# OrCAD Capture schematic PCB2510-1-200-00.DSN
size Custom; title: .; rev: 00; note: NFC EXPANSION BOARD OM5578/PN7150S
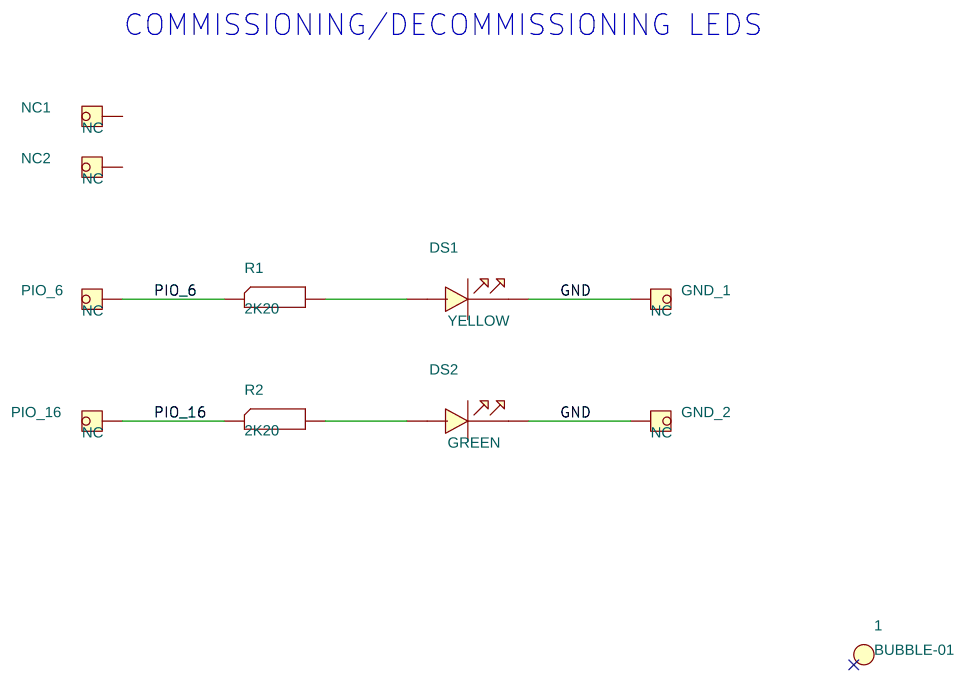
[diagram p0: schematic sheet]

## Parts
1  BUBBLE-01  [BUBBLE_DIAM8]
DS1  YELLOW  [LED_0603_A_K]
DS2  GREEN  [LED_0603_A_K]
GND_1  NC  [TROU1MM1_PAST1MM6]
GND_2  NC  [TROU1MM1_PAST1MM6]
NC1  NC  [TROU1MM1_PAST1MM6]
NC2  NC  [TROU1MM1_PAST1MM6]
PIO_6  NC  [TROU1MM1_PAST1MM6]
PIO_16  NC  [TROU1MM1_PAST1MM6]
R1  2K20  [R0603]
R2  2K20  [R0603]

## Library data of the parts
1 = BUBBLE: Designation: Printed_Circuit_Board:PCB2510-1; Manufacturer_reference: PCB2510-1; Part Number: CI-PCB2510-1; Part Type: BUBBLE-001_CI; Supplier: ASCO
DS1 = LED: Designation: LED 0603 YELLOW HSMY-C190; Package: 0603; Part Number: 0-00-001289; Supplier: FARNELL
DS2 = LED: Designation: LED 0603 GREEN HSMG-C190; Package: 0603; Part Number: 0-00-001303; Supplier: FARNELL
GND_1 GND_2 NC1 NC2 PIO_6 PIO_16 = TP: Designation: !!! NOT CONNECTED !!! Mechanical holes 1mm1; Part Number: NC-MECA-PAST160_P110; Part Type: MECA_HOLE
R1 R2 = RES: Alt_Symbols: 0603R; Designation: Resistor 0603 2K20 1% 100ppm -; MANUFACTURER_REFERENCE: VISHAY (CRCW06032K20FKEA); PACKAGE: 603; PPM: 100ppm; Part Number: 0-00-302487A; SUPPLIER: RADIOSPARES; TOL: 1%; Type: CMS

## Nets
GND: DS1.K DS2.K GND_1.1 GND_2.1
PIO_6: PIO_6.1 R1.1
PIO_16: PIO_16.1 R2.1
N2331965: DS1.A R1.2
N2332086: DS2.A R2.2

Not connected (* = marked no-connect by the designer): 1 1*; NC1 1; NC2 1

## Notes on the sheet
- COMMISSIONING/DECOMMISSIONING LEDS
